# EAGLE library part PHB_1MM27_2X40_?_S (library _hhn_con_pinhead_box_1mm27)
Pin Header Box-Type, 1.27mm/0.5"/50mil Pitch, 2x40 Circuits, single gates in schematic Note: see library description for an important note about THT-version
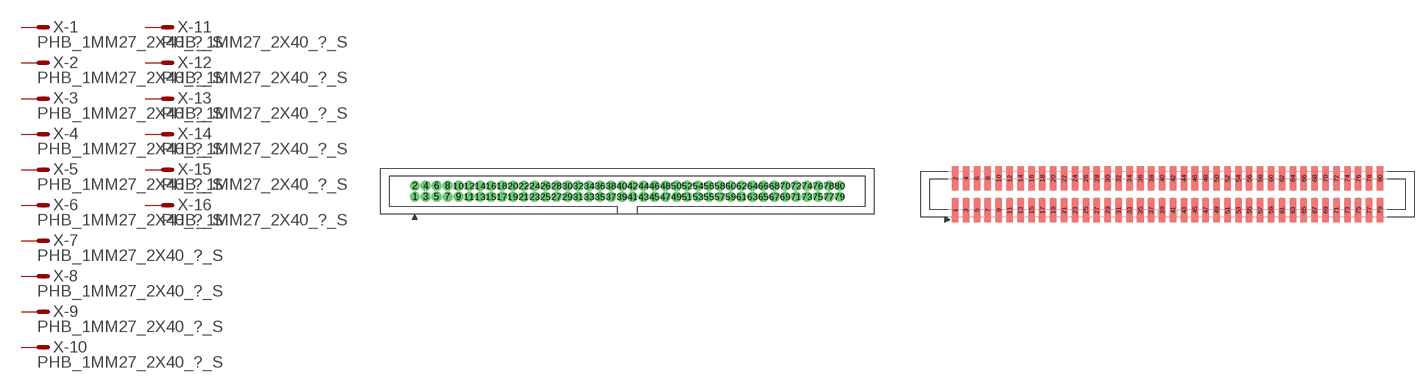
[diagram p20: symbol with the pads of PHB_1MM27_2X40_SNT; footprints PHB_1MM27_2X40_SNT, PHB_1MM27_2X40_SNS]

Designator prefix X; gates -1=M -2=M -3=M -4=M -5=M -6=M -7=M -8=M -9=M -10=M -11=M -12=M -13=M -14=M -15=M -16=M -17=M -18=M -19=M -20=M -21=M -22=M -23=M -24=M -25=M -26=M -27=M -28=M -29=M -30=M -31=M -32=M -33=M -34=M -35=M -36=M -37=M -38=M -39=M -40=M -41=M -42=M -43=M -44=M -45=M -46=M -47=M -48=M -49=M -50=M -51=M -52=M -53=M -54=M -55=M -56=M -57=M -58=M -59=M -60=M -61=M -62=M -63=M -64=M -65=M -66=M -67=M -68=M -69=M -70=M -71=M -72=M -73=M -74=M -75=M -76=M -77=M -78=M -79=M -80=M

## PHB_1MM27_2X40_SNT_S  [PHB_1MM27_2X40_SNT]
1  -1:S  pas
2  -2:S  pas
3  -3:S  pas
4  -4:S  pas
5  -5:S  pas
6  -6:S  pas
7  -7:S  pas
8  -8:S  pas
9  -9:S  pas
10  -10:S  pas
11  -11:S  pas
12  -12:S  pas
13  -13:S  pas
14  -14:S  pas
15  -15:S  pas
16  -16:S  pas
17  -17:S  pas
18  -18:S  pas
19  -19:S  pas
20  -20:S  pas
21  -21:S  pas
22  -22:S  pas
23  -23:S  pas
24  -24:S  pas
25  -25:S  pas
26  -26:S  pas
27  -27:S  pas
28  -28:S  pas
29  -29:S  pas
30  -30:S  pas
31  -31:S  pas
32  -32:S  pas
33  -33:S  pas
34  -34:S  pas
35  -35:S  pas
36  -36:S  pas
37  -37:S  pas
38  -38:S  pas
39  -39:S  pas
40  -40:S  pas
41  -41:S  pas
42  -42:S  pas
43  -43:S  pas
44  -44:S  pas
45  -45:S  pas
46  -46:S  pas
47  -47:S  pas
48  -48:S  pas
49  -49:S  pas
50  -50:S  pas
51  -51:S  pas
52  -52:S  pas
53  -53:S  pas
54  -54:S  pas
55  -55:S  pas
56  -56:S  pas
57  -57:S  pas
58  -58:S  pas
59  -59:S  pas
60  -60:S  pas
61  -61:S  pas
62  -62:S  pas
63  -63:S  pas
64  -64:S  pas
65  -65:S  pas
66  -66:S  pas
67  -67:S  pas
68  -68:S  pas
69  -69:S  pas
70  -70:S  pas
71  -71:S  pas
72  -72:S  pas
73  -73:S  pas
74  -74:S  pas
75  -75:S  pas
76  -76:S  pas
77  -77:S  pas
78  -78:S  pas
79  -79:S  pas
80  -80:S  pas

## PHB_1MM27_2X40_SNS_S  [PHB_1MM27_2X40_SNS]
Pads as for PHB_1MM27_2X40_SNT

## Footprint PHB_1MM27_2X40_SNT (pad centres in mm)
Pin Header Box-Type, 1.27mm Pitch, 2x40 circuits, Straight, No Locking, THT Important Note: Diameter in this lbr is set to a specific value (NOT 'auto' = 0), this is ignored by actual eagle versions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
drill 0.65 pad 1 round: 1 -24.765,-0.635; 2 -24.765,0.635; 3 -23.495,-0.635; 4 -23.495,0.635; 5 -22.225,-0.635; 6 -22.225,0.635; 7 -20.955,-0.635; 8 -20.955,0.635; 9 -19.685,-0.635; 10 -19.685,0.635; 11 -18.415,-0.635; 12 -18.415,0.635; 13 -17.145,-0.635; 14 -17.145,0.635; 15 -15.875,-0.635; 16 -15.875,0.635; 17 -14.605,-0.635; 18 -14.605,0.635; 19 -13.335,-0.635; 20 -13.335,0.635; 21 -12.065,-0.635; 22 -12.065,0.635; 23 -10.795,-0.635; 24 -10.795,0.635; 25 -9.525,-0.635; 26 -9.525,0.635; 27 -8.255,-0.635; 28 -8.255,0.635; 29 -6.985,-0.635; 30 -6.985,0.635; 31 -5.715,-0.635; 32 -5.715,0.635; 33 -4.445,-0.635; 34 -4.445,0.635; 35 -3.175,-0.635; 36 -3.175,0.635; 37 -1.905,-0.635; 38 -1.905,0.635; 39 -0.635,-0.635; 40 -0.635,0.635; 41 0.635,-0.635; 42 0.635,0.635; 43 1.905,-0.635; 44 1.905,0.635; 45 3.175,-0.635; 46 3.175,0.635; 47 4.445,-0.635; 48 4.445,0.635; 49 5.715,-0.635; 50 5.715,0.635; 51 6.985,-0.635; 52 6.985,0.635; 53 8.255,-0.635; 54 8.255,0.635; 55 9.525,-0.635; 56 9.525,0.635; 57 10.795,-0.635; 58 10.795,0.635; 59 12.065,-0.635; 60 12.065,0.635; 61 13.335,-0.635; 62 13.335,0.635; 63 14.605,-0.635; 64 14.605,0.635; 65 15.875,-0.635; 66 15.875,0.635; 67 17.145,-0.635; 68 17.145,0.635; 69 18.415,-0.635; 70 18.415,0.635; 71 19.685,-0.635; 72 19.685,0.635; 73 20.955,-0.635; 74 20.955,0.635; 75 22.225,-0.635; 76 22.225,0.635; 77 23.495,-0.635; 78 23.495,0.635; 79 24.765,-0.635; 80 24.765,0.635

## Footprint PHB_1MM27_2X40_SNS (pad centres in mm)
Pin Header Box-Type, 1.27mm Pitch, 2x40 circuits, Straight, No Locking, SMT
smd 0.76 x 2.8: 1 -24.765,-1.85; 2 -24.765,1.85; 3 -23.495,-1.85; 4 -23.495,1.85; 5 -22.225,-1.85; 6 -22.225,1.85; 7 -20.955,-1.85; 8 -20.955,1.85; 9 -19.685,-1.85; 10 -19.685,1.85; 11 -18.415,-1.85; 12 -18.415,1.85; 13 -17.145,-1.85; 14 -17.145,1.85; 15 -15.875,-1.85; 16 -15.875,1.85; 17 -14.605,-1.85; 18 -14.605,1.85; 19 -13.335,-1.85; 20 -13.335,1.85; 21 -12.065,-1.85; 22 -12.065,1.85; 23 -10.795,-1.85; 24 -10.795,1.85; 25 -9.525,-1.85; 26 -9.525,1.85; 27 -8.255,-1.85; 28 -8.255,1.85; 29 -6.985,-1.85; 30 -6.985,1.85; 31 -5.715,-1.85; 32 -5.715,1.85; 33 -4.445,-1.85; 34 -4.445,1.85; 35 -3.175,-1.85; 36 -3.175,1.85; 37 -1.905,-1.85; 38 -1.905,1.85; 39 -0.635,-1.85; 40 -0.635,1.85; 41 0.635,-1.85; 42 0.635,1.85; 43 1.905,-1.85; 44 1.905,1.85; 45 3.175,-1.85; 46 3.175,1.85; 47 4.445,-1.85; 48 4.445,1.85; 49 5.715,-1.85; 50 5.715,1.85; 51 6.985,-1.85; 52 6.985,1.85; 53 8.255,-1.85; 54 8.255,1.85; 55 9.525,-1.85; 56 9.525,1.85; 57 10.795,-1.85; 58 10.795,1.85; 59 12.065,-1.85; 60 12.065,1.85; 61 13.335,-1.85; 62 13.335,1.85; 63 14.605,-1.85; 64 14.605,1.85; 65 15.875,-1.85; 66 15.875,1.85; 67 17.145,-1.85; 68 17.145,1.85; 69 18.415,-1.85; 70 18.415,1.85; 71 19.685,-1.85; 72 19.685,1.85; 73 20.955,-1.85; 74 20.955,1.85; 75 22.225,-1.85; 76 22.225,1.85; 77 23.495,-1.85; 78 23.495,1.85; 79 24.765,-1.85; 80 24.765,1.85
